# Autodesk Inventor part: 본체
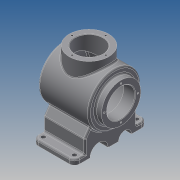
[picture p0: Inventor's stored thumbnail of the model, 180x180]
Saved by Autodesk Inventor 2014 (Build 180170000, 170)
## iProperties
Created: 2018-08
Part Number: 본체
Material: Generic
Document SubType Name: Modeling
Designer: kb542
Density: 1 g/cm^3
Appearance: Default
Author: kb542
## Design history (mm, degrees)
sketch "스케치1"
  geometry: L1 (-60, 0)-(60, 0); L2 (-60, 38)-(-48, 38); L3 (-48, 38)-(-48, 50); L4 (-48, 50)-(48.671, 50); L5 (42.163, 40)-(-38, 40); L6 (-38, 40)-(-38, 27); L7 (-38, 27)-(-60, 27); L8 (-60, 27)-(-60, 38); A1 r 116 centre (-56, 0) between (60, 0) and (48.671, 50); A2 r 106 centre (-56, 0) between (50, 0) and (42.163, 40); 2 further points
  constraints: 16 end point, 4 parallel, 4 point on circle, 3 perpendicular, 2 centre point, 2 point on line, 1 coincident, 1 horizontal, 1 midpoint, 1 vertical alignment
  dimensions: "d0" = 116 radius of A1; "d1" = 76 diameter of L2 L1; "d2" = 100 diameter of L4 L1; "d3" = 12 distance of L2.start L2.end; "d5" = 108 distance from line of L1.end L3; "d6" = 10 radial gap between concentric circles of A2 A1; "d7" = 54 diameter of L7 L1; "d8" = 80 diameter of L5 L1; "d9" = 22 distance of L6.end L7.end
revolve "회전1" sketch "스케치1" stored, may be unused: angle "d10" = 90 deg
node "작업 평면3"
sketch "스케치10"
  geometry: L1 (-40, 70)-(40, 70); L2 (40, 70)-(40, -70); L3 (40, -70)-(-40, -70); L4 (-40, -70)-(-40, 70); L5 (60, 38)-(60, -38) reference; 2 further points
  constraints: 8 end point, 2 parallel, 1 horizontal, 1 horizontal alignment, 1 midpoint, 1 perpendicular
  dimensions: "d89" = 140 distance of L3.end L1.start; "d90" = 80 distance of L1.start L1.end; "d91" = 20 distance between parallel lines of L5 L2
extrude "돌출6" join sketch "스케치10" distance "d92" = 10; taper "d93" = 0 deg
sketch "스케치11"
  geometry: L1 (0, 140)-(-10, 140) reference; L2 (-10, 0)-(-10, 140) reference; L3 (0, 0)-(-10, 0) reference; L4 (-10, 140)-(0, 140) reference; L5 (0, 140)-(0, 0) reference; L6 (0, 0)-(-10, 0) reference; L7 (-10, 0)-(-10, 140) reference; L8 (-51.154, 30.649)-(-35.946, 20); L9 (-35.946, 20)-(-10, 20); L10 (-51.154, 109.351)-(-35.946, 120); L11 (-35.946, 120)-(-10, 120); C1 r 27 at (-82, 70) reference; A1 r 50 centre (-82, 70) between (-51.154, 30.649) and (-51.154, 109.351) reference; 1 further point
  constraints: 8 end point, 2 perpendicular, 2 point on circle, 2 point on line, 2 vertical alignment
  dimensions: "d94" = 35 deg angle of L1 L10; "d95" = 35 deg angle of L3 L8; "d96" = 20 distance between parallel lines of L3 L9; "d97" = 20 distance between parallel lines of L11 L1
extrude "돌출7" join sketch "스케치11" distance "d98" = 80; taper "d99" = 0 deg
sketch "스케치13"
  geometry: L1 (0, 0)-(0, 140) reference; C1 r 12.5 at (0, 97.5); C2 r 17.5 at (0, 47.5); A1 r 50 centre (82, 70) between (51.154, 109.351) and (51.154, 30.649) reference
  constraints: 2 centre point, 2 point on line
  dimensions: "d100" = 12.5 radius of C1; "d101" = 17.5 radius of C2; "d102" = 22.5 vertical distance of C2.centre A1.centre; "d103" = 27.5 vertical distance of A1.centre C1.centre
extrude "돌출8" cut sketch "스케치13" stored distance "d104" = 80; taper "d105" = 0 deg
node "작업 평면5"
sketch "스케치15"
  geometry: L1 (60, 38)-(60, -38) reference; C1 r 38 at (-2, 0); 1 further point
  constraints: 1 centre point, 1 horizontal alignment
  dimensions: "d107" = 62 distance from line of L1 C1.centre; "d108" = 76 diameter of C1
extrude "돌출9" join sketch "스케치15" stored distance "d109" = 80; taper "d110" = 0 deg
sketch "스케치16"
  geometry: C1 r 38 at (0, 0) reference; C2 r 27 at (0, 0); 1 further point
  constraints: 1 centre point, 1 coincident
  dimensions: "d111" = 54 diameter of C2
extrude "돌출10" cut sketch "스케치16" stored distance "d112" = 80; taper "d113" = 0 deg
sketch "스케치17"
  geometry: C1 r 27 at (0, 0) reference; C2 r 38 at (0, 0) reference; A1 r 32.5 centre (0, 0) between (0, 32.5) and (32.5, 0); 3 further points
  constraints: 4 point on circle, 2 horizontal alignment, 2 vertical alignment, 1 centre point, 1 coincident
  dimensions: "d114" = 65 diameter of A1
hole "구멍4" sketch "스케치17" at (0, 32.5), (32.5, 0), (-32.5, 0), (0, -32.5) diameter "d115" = 3.459; stored, may be unused: countersink angle "d119" = 90 deg, drill point angle "d121" = 118 deg; dims "d116" = 8, "d117" = 4, "d118" = 2, "d120" = 10
sketch "스케치18"
  geometry: C1 r 38 at (0, 0) reference; C2 r 27 at (0, 0) reference; A1 r 32.5 centre (0, 0) between (0, 32.5) and (-32.5, 0); 2 further points
  constraints: 4 point on circle, 2 horizontal alignment, 2 vertical alignment, 1 centre point, 1 coincident
  dimensions: "d122" = 65 diameter of A1
hole "구멍5" sketch "스케치18" at (0, 32.5), (-32.5, 0), (32.5, 0), (0, -32.5) diameter "d123" = 3.459; stored, may be unused: countersink angle "d127" = 90 deg, drill point angle "d129" = 118 deg; dims "d124" = 8, "d125" = 4, "d126" = 2, "d128" = 10
fillet "모깎기2" dims "d130" = 10
sketch "스케치19"
  geometry: L1 (40, 60)-(40, 50) reference; L2 (40, 50)-(40, 35) reference; L3 (40, 35)-(-40, 35) reference; L4 (-40, 35)-(-40, 50) reference; L5 (-40, 50)-(40, 50) reference; L6 (-30, 70)-(30, 70) reference; L7 (-40, 50)-(-40, 60) reference; L8 (40, 20)-(40, -8.139) reference; L9 (40, -8.139)-(-40, -8.139) reference; L10 (-40, -8.139)-(-40, 20) reference; L11 (-40, 20)-(40, 20) reference; L12 (40, -36.861)-(40, -50) reference; L13 (40, -50)-(40, -60) reference; L14 (30, -70)-(-30, -70) reference; L15 (-40, -60)-(-40, -50) reference; L16 (40, -50)-(-40, -50) reference; L17 (-40, -36.861)-(40, -36.861) reference; L18 (-40, -50)-(-40, -36.861) reference; A1 r 10 centre (30, 60) between (40, 60) and (30, 70) reference; A2 r 10 centre (-30, 60) between (-30, 70) and (-40, 60) reference; A3 r 10 centre (30, -60) between (30, -70) and (40, -60) reference; A4 r 10 centre (-30, -60) between (-40, -60) and (-30, -70) reference; 5 further points
  constraints: 4 coincident
hole "구멍6" sketch "스케치19" at (-30, 60), (30, 60), (30, -60), (-30, -60) diameter "d131" = 8; stored, may be unused: countersink angle "d135" = 90 deg, drill point angle "d137" = 0 deg; dims "d132" = 8, "d133" = 4, "d134" = 2, "d136" = 10
node "작업 평면6"
sketch "스케치21"
  geometry: C1 r 32.5 at (0, 0); 1 further point
  constraints: 1 centre point, 1 coincident, 1 other
  dimensions: "d140" = 65 diameter of C1
feature "엠보싱1" sketch "스케치21" dims "d0" = 116, "d1" = 76, "d2" = 100, "d3" = 12, "d5" = 108, "d6" = 10, "d7" = 54, "d8" = 80, "d9" = 22, "d141" = 0.5, "d142" = 0
fillet "모깎기3" dims "d143" = 3
fillet "모깎기4" dims "d144" = 3
fillet "모깎기5" dims "d145" = 3
chamfer "모따기1" distance "d146" = 1; stored, may be unused: second distance "d147" = 2, angle "d148" = 45 deg
fillet "모깎기6" dims "d149" = 3
node "솔리드1"
node "절단 모서리 투영3"
node "절단 모서리 투영4"
other parameters: "d88" = -82, "d106" = 65
